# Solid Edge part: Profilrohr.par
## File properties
Username: bmolnar
Dokumentum tartalom típus: 0
Author: bmolnar
Last saved by: bmolnar
Revision: 86
Sűrűség: 0,000 kg/m^3
Pontosság: 0,990
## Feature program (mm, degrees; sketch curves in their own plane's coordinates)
base feature "unnamed BaseFeature 1"
thread "Menet_1"  ThreadDepth = 9.3 mm
thread "unnamed Thread 1"
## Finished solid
Body 1: solid body, 157 faces, 384 edges, 249 vertices.
  Faces by surface: plane 79, cylinder 66, cone 8, torus 4
  Edges by curve: line 236, circle 140, curve on surface 8
Bounding box of the edges (mm; curved faces can reach further): 100.000 x 105.000 x 146.000, from (-50, -50, 0) to (50, 55, 146).
Cylindrical faces by radius (mm): R0.2 x24, R2.15 x2, R4.5 x4, R5.5 x4, R5.7225 x4, R7 x8, R8.5 x8, R40 x1, R40.1 x1, R40.85 x2, R41.05 x2, R42.8 x2, R67.3474 x1, R67.5 x3
Conical faces (half-angle, radius in mm at the cone's reference point): 30 deg R40.325 x2, 30 deg R41.1387 x2, 45 deg R6.0725 x2, 45 deg R41.15 x2
Toroidal faces (ring radius, tube radius in mm): R42.6 r0.2 x4
Planar faces by outward normal: +x 9, +y 11, +z 9, -x 9, -y 9, -z 8, oblique 24
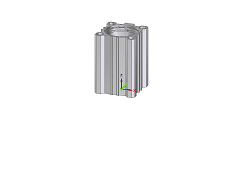
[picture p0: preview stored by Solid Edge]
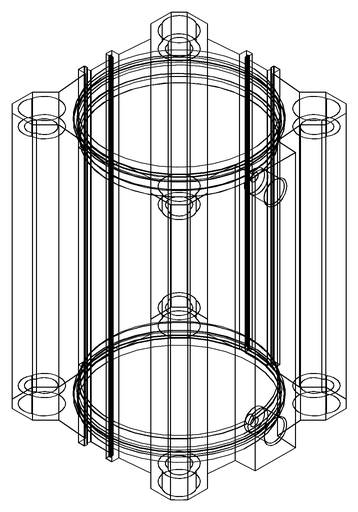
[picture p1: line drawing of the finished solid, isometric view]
